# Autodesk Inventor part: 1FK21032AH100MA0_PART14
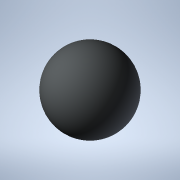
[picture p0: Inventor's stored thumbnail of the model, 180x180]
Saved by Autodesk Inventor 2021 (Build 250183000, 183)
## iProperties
Created: 2025-04
Part Number: 1FK21032AH100MA0_PART14
Material: Generic
Catalog Web Link: www.3dfindit.com
Description: -Servo synchronous motor
Document SubType Name: Modeling
Designer: psAdmin
Mass: 0.113097 g
Surface Area: 1.13097 cm^2
Volume: 0.113097 cm^3
Density: 1 g/cm^3
Appearance: PSOLRGB-212-217-219
Category: PARTsolutions
Title: 1FK21032AH100MA0_PART14
Author: Cadenas PARTsolutions
Comments: Servo synchronous motor
Sending System: PARTsolutions
Preprocessor: ST-DEVELOPER v19.3
PSOL_IDENT_0: {$CADENAS_DATA/23d-libs/siemens_ag/_cat_/12/33/1fk21032ah100ma0.prj},216 {VTYP=3D},{NB=1FK21032AH100
PSOL_IDENT_1: MA0_PART14},{LINA=1FK21032AH100MA0_PART14},{NN=1FK21032AH100MA0_PART14},{NOPRJ=TRUE},{DATE=19.08.202
PSOL_IDENT_2: 5 14:00:27},{GEOMDATE=30.07.2025 02:02:58},{VERSION=},{LINEID=10},{WBVAR=},{WBNUMERIC=}  {NB=1FK2103
PSOL_IDENT_3: 2AH100MA0_PART14},{LINA=1FK21032AH100MA0_PART14},{KT=DUMMY},{PREVIEW=../../../_pool_/d3/78/p_d211_xx
PSOL_IDENT_4: _00934j.png},{DESCSHORT=SIMOTICS S-1FK2 HD, SINAMICS S210 3AC 400V-480V, 0.59 Nm, 4500 rpm},{DESCLON
PSOL_IDENT_5: G=SIMOTICS S-1FK2 HD servo motor M0=0.64 Nm; PN = 0.28 kW at nN=4500 rpm (380-480 V); PN = 0.167 kW
PSOL_IDENT_6: at nN=2500 rpm (200-240 V); with holding brake; degree of protection IP64; cylindrical shaft D14 x 3
PSOL_IDENT_7: 0 mm; absolute encoder 22-bit + 12-bit multiturn (encoder AM22DQC); with OCC interface; plug size M1
PSOL_IDENT_8: 7, rotatable; SIMOTICS S-1FK2 servomotorfor a wide range of uses in industrial environments. SIMOTIC
PSOL_IDENT_9: S S‑1FK2 servomotors are compact synchronous motors with a high dynamic performance that set themsel
PSOL_IDENT_10: ves apart as a result of their high power density, degree of protection and overload capability. The
PSOL_IDENT_11: motors are available in two variants: as High Dynamic variant (highest dynamic performance as a res
PSOL_IDENT_12: ult of the low intrinsic moment of inertia for applications demanding a high dynamic performance wit
PSOL_IDENT_13: h low moved masses) - and as Compact variant (precise and stable closed-loop control for medium up t
PSOL_IDENT_14: o large moved masses as a result of a medium intrinsic moment of inertia). SIMOTICSS‑1FK2 servomotor
PSOL_IDENT_15: s fully exploit their strengths in a system with the SINAMICSS210 frequency converter and simple con
PSOL_IDENT_16: nection using the one cable connection (OCC). Advantages include the short control and positioning t
PSOL_IDENT_17: imes, fast and precise correction of disturbing quantities as well as stable control with a high dyn
PSOL_IDENT_18: amic performance. The servo motors can be configured to address a wide range of requirements. For ex
PSOL_IDENT_19: ample with and without holding brake, IP64 or IP65 degree of protection, singleturn or multiturn abs
PSOL_IDENT_20: olute encoders - to name just a few. Further, the servomotors are available in different shaft heigh
PSOL_IDENT_21: ts extending from 20 to 100. A shaft sealing ring is available to achieve an IP65 degree of protecti
PSOL_IDENT_22: on and for subsequent mounting at the motor or as spare part. SIMOTICS - the optimum motor for each
PSOL_IDENT_23: and every motion control application.},{INTNO=195125315563},{SUPPLIERALTNO=1FK2103-2AH10-0MA0},{MANU
PSOL_IDENT_24: ID=1FK21032AH100MA0},{MANUNAME=Siemens},{MANUTYPEDESC=SYNCHRONOUS MOTOR 1FK2 HD 0,64 NM},{AAU732=SIM
PSOL_IDENT_25: OTICS},{AAO057=S-1FK2},{AAU734=SIMOTICS S-1FK2 HD servo motor M0=0.64 Nm; PN = 0.28 kW at nN=4500 rp
PSOL_IDENT_26: m (380-480 V); PN = 0.167 kW at nN=2500 rpm (200-240 V); with holding brake; degree of protection IP
PSOL_IDENT_27: 64; cylindrical shaft D14 x 30 mm; absolute encoder 22-bit + 12-bit multiturn (encoder AM22DQC); wit
PSOL_IDENT_28: h OCC interface; plug size M17, rotatable;},{AAW338=SYNCHRONOUS MOTOR 1FK2 HD 0,64 NM},{AAO742=SIMOT
PSOL_IDENT_29: ICS},{AAO663=4034106444723},{NOCUPEROU=1},{PRICEQUANTITY=1},{QUANTITYMIN=1},{QUANTITYINT=1},{CTN=850
PSOL_IDENT_30: 15100},{COO=RO},{AAO676=1FK2103-2AH10-0MA0},{AAO677=Siemens AG},{ORDERUNIT=C62},{CONTENTUNIT=C62}
NB: 1FK21032AH100MA0_PART14
NT: Servo synchronous motor
NBSYN: $MANUID._PART14
LINA: 1FK21032AH100MA0_PART14
CATALOG: SIEMENS
PREVIEW: ../../../_pool_/d3/78/p_d211_xx_00934j.png
DESCSHORT: SIMOTICS S-1FK2 HD, SINAMICS S210 3AC 400V-480V, 0.59 Nm, 4500 rpm
DESCLONG: SIMOTICS S-1FK2 HD servo motor M0=0.64 Nm; PN = 0.28 kW at nN=4500 rpm (380-480 V); PN = 0.167 kW at nN=2500 rpm (200-240 V); with holding brake; degree of prot
INTNO: 195125315563
SUPPLIERALTNO: 1FK2103-2AH10-0MA0
MANUID: 1FK21032AH100MA0
MANUNAME: Siemens
MANUTYPEDESC: SYNCHRONOUS MOTOR 1FK2 HD 0,64 NM
AAU732: SIMOTICS
AAO057: S-1FK2
AAU734: SIMOTICS S-1FK2 HD servo motor M0=0.64 Nm; PN = 0.28 kW at nN=4500 rpm (380-480 V); PN = 0.167 kW at nN=2500 rpm (200-240 V); with holding brake; degree of prot
AAW338: SYNCHRONOUS MOTOR 1FK2 HD 0,64 NM
AAO742: SIMOTICS
AAO663: 4034106444723.0
NOCUPEROU: 1
PRICEQUANTITY: 1
QUANTITYMIN: 1
QUANTITYINT: 1
CTN: 85015100
COO: RO
ARTICLENO: 1FK21032AH100MA0_PART14
BOMINFO: 1FK21032AH100MA0_PART14
CREATOR: CADENAS GmbH
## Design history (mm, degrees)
feature "2025_04_17_15_06_16_0705"
body "Solid1"
